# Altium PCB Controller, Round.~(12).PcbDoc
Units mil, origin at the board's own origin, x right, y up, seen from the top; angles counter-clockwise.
Board outline 1800 x 1800 mil, 2 copper layers (Top Layer, Bottom Layer); 50 components, 49 nets, 210 pads, 0 vias.
Unrouted connection lines stored in the file: 130.
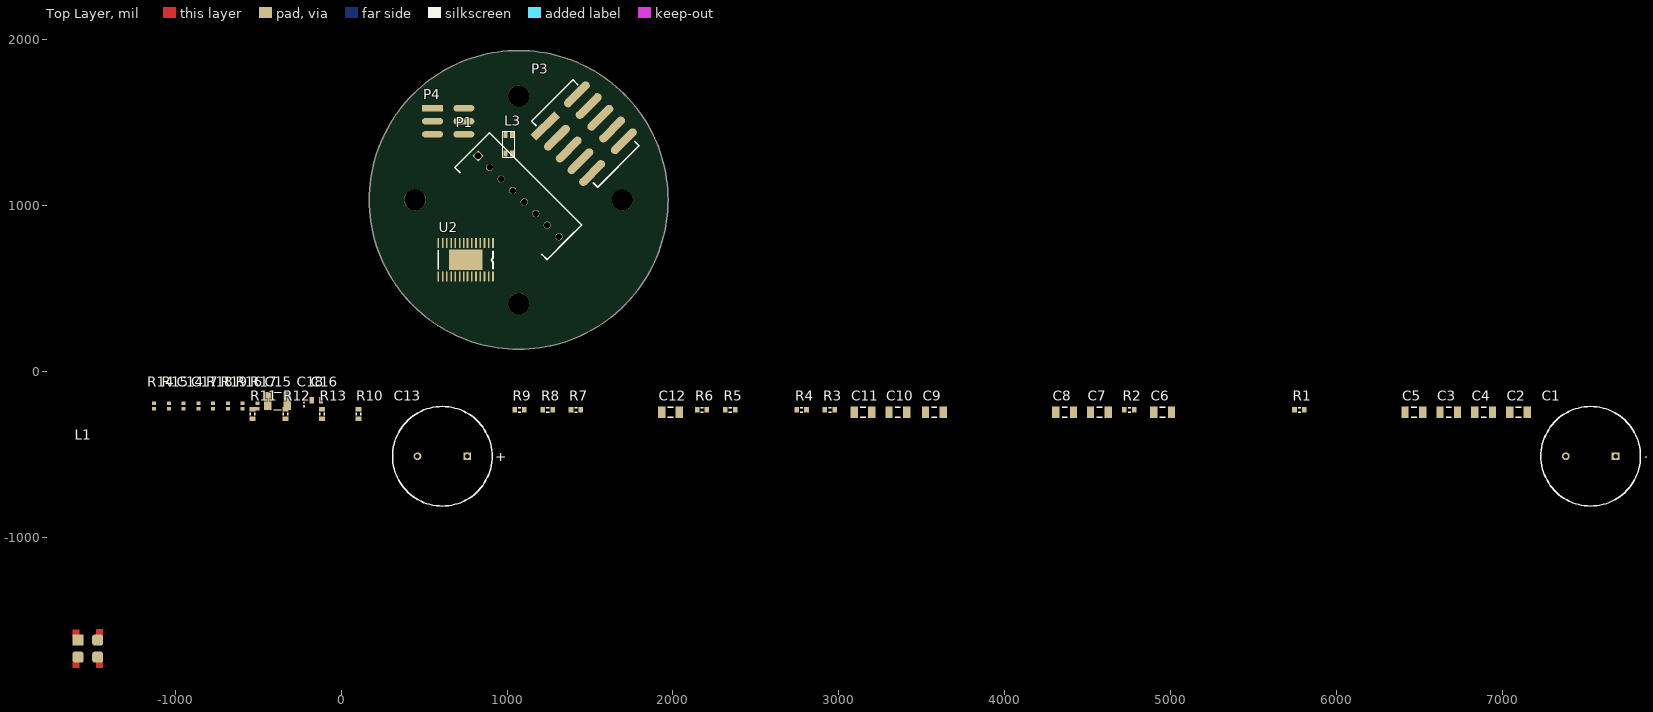
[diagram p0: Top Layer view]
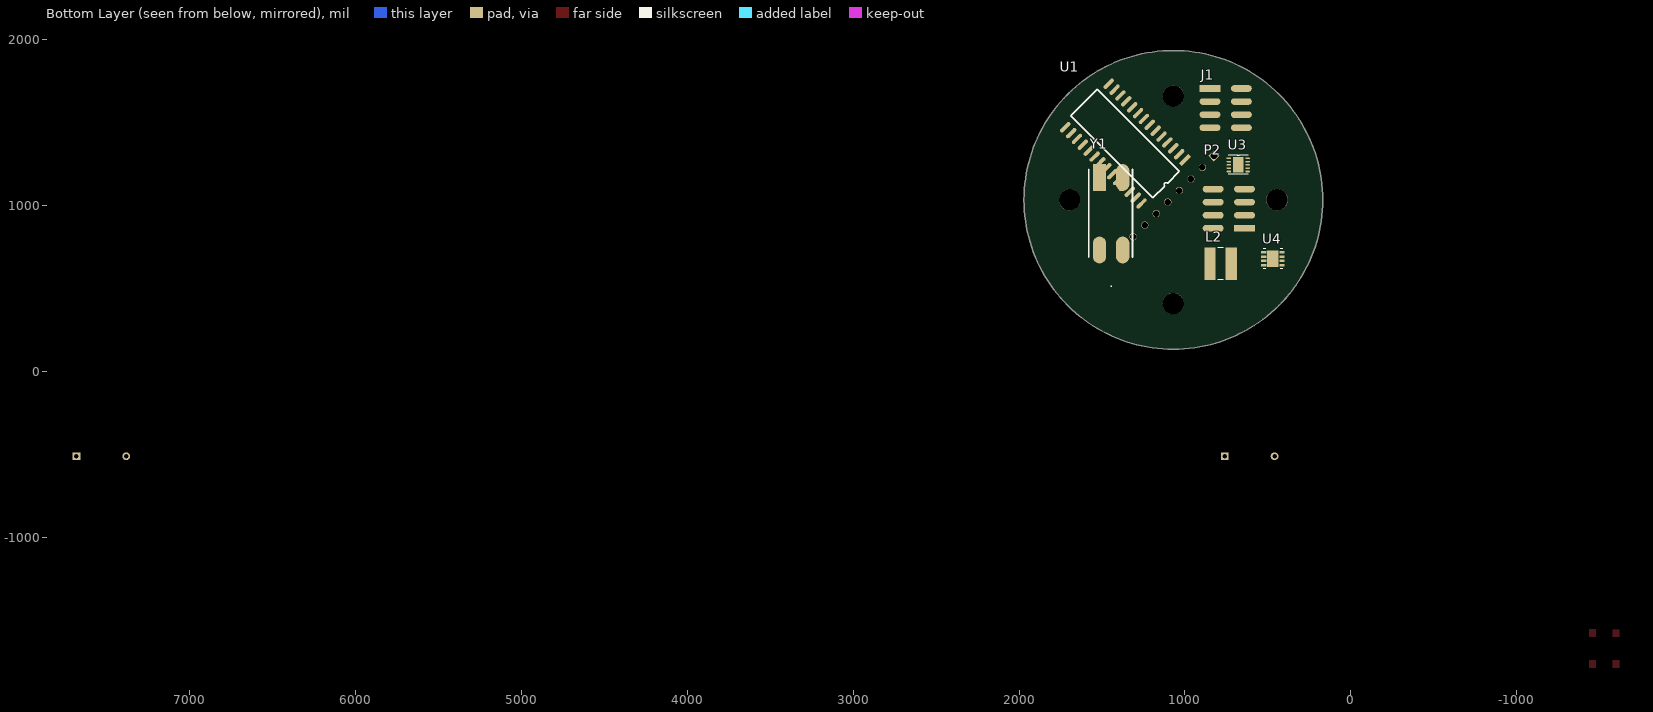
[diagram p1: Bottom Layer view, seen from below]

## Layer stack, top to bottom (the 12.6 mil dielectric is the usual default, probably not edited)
Top Layer: signal copper 1.4
Dielectric: dielectric 12.6, FR-4, Dk 4.8
Bottom Layer: signal copper 1.4

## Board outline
1070,135 cw(c1070,1035) 170,1035 cw(c1070,1035) 1070,1935 cw(c1070,1035) 1970,1035 cw(c1070,1035)

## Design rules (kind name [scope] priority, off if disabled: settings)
Clearance [All] p1: gap=10
PolygonConnect [All] p1: connectstyle=Relief reliefconductorwidth=10 reliefentries=4 polygonreliefangle="90 Angle"
RoomDefinition Controller [InComponentClass('Controller')] p1: confinementstyle=ConfineIn formatcopy=TRUE lockcomponents=FALSE outline -1190,-1020 8060,-1020 8060,-100 -1190,-100
RoutingVias [All] p1: holewidth=28 width=50 viastyle="Through Hole" minholewidth=28 minwidth=50 maxholewidth=28 maxwidth=50
SilkscreenOverComponentPads [All] p1: minsilkscreentomaskgap=10
SolderMaskExpansion [All] p1: expansion=4
Width [All] p1: maxlimit=10 minlimit=10 preferedwidth=10
27 further rules are at their usual default settings.

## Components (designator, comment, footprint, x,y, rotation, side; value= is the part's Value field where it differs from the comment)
C1 "Cap Pol1" RB7.6-15 7530,-510 r0 top
C2 "Cap Semi" C1206 7095,-245 r0 top
C3 "Cap Semi" C1206 6675,-245 r0 top
C4 "Cap Semi" C1206 6885,-245 r0 top
C5 "Cap Semi" C1206 6465,-245 r0 top
C6 "Cap Semi" C1206 4950,-245 r0 top
C7 "Cap Semi" C1206 4570,-245 r0 top
C8 "Cap Semi" C1206 4360,-245 r0 top
C9 "Cap Semi" C1206 3575,-245 r0 top
C10 "Cap Semi" C1206 3355,-245 r0 top
C11 "Cap Semi" C1206 3145,-245 r0 top
C12 "Cap Semi" C1206 1985,-245 r0 top
C13 "Cap Pol1" RB7.6-15 610,-510 r0 top
C14 "C1005X7R1E103K" 0402 -949.05,-206.31 r90 top
C15 "C3225X7R2A225K230AB" 1210 -383.13,-177 r0 top
C16 "C1608X5R0J106M" 0603 -148.84,-172.98 r0 top
C17 "C0402C330J5GAC" 0402 -860.06,-206.31 r90 top
C18 "GRM033R61A472KA01D" 0201 -223.84,-197.98 r90 top
J1 "M80-8280842" M8082808DIL 660,1470 r0 bottom
L1 "DLW5BTM501SQ2" DLW5A_5B -1585,-1720 r90 top
L2 "LPS5030-823MLB" LPS5030 785,650 r180 bottom
L3 "SRF3216-222Y" SRF3216 1030,1315 r180 top
P1 "MKS 1658-6-0-808" MKS_1658_A_KF 825,1300 r315 top
P2 "M80-8280842" M8082808DIL 830,1100 r180 bottom
P3 "N2510-6V0C-RB-WD" N2510_SMD 1230,1480 r45 top
P4 "M80-8280642" M8082806DIL 740,1430 r180 top
R1 "Res3" J1-0603 5775,-230 r0 top
R2 "Res3" J1-0603 4750,-230 r0 top
R3 "Res3" J1-0603 2945,-230 r0 top
R4 "Res3" J1-0603 2775,-230 r0 top
R5 "Res3" J1-0603 2345,-230 r0 top
R6 "Res3" J1-0603 2175,-230 r0 top
R7 "Res3" J1-0603 1415,-230 r0 top
R8 "Res3" J1-0603 1245,-230 r0 top
R9 "Res3" J1-0603 1075,-230 r0 top
R10 "Res3" J1-0603 105,-255 r90 top
R11 "Res3" J1-0603 -535,-255 r90 top
R12 "Res3" J1-0603 -335,-255 r90 top
R13 "Res3" J1-0603 -115,-255 r90 top
R14 "CRCW0402665KFKED" 0402 -1127.02,-206.31 r90 top
R15 "CRCW040253K6FKED" 0402 -1038.03,-206.31 r90 top
R16 "CRCW040246K4FKED" 0402 -593.11,-206.31 r90 top
R17 "CRCW040242K2FKED" 0402 -504.13,-206.31 r90 top
R18 "CRCW040210K0FKED" 0402 -771.08,-206.31 r90 top
R19 "CRCW040280K6FKED" 0402 -682.1,-206.31 r90 top
U1 "PIC_SERVO_SC" SOP28 1000,1275 r315 bottom
U2 "DRV8313" ? 915,775 r270 top
U3 "LTC2864xDD" DD10 735,1285 r180 bottom
U4 "TPS54061DRBR" S-PVSON-N8 470,680 r180 bottom
Y1 "MA-506 10.0000M-C0" MA506 1515,1170 r180 bottom

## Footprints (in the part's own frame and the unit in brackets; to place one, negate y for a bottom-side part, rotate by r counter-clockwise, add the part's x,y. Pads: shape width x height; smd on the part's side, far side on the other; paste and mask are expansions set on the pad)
0201 [mil]
  rect 14x13 smd: 1(-11.5,0) 2(11.5,0)
0402 [mil]
  rect 22x24 smd: 1(-16.5,0) 2(16.5,0)
0603 [mil]
  rect 26x38 smd: 1(-27.5,0) 2(27.5,0)
1210 [mil]
  rect 44x106 smd: 1(-59,0) 2(59,0)
  silkscreen extent -24,-53 24,53
C1206 [mm] "Chip Capacitor, Body 3.2x1.6mm, IPC High Density"
  rect 1.1x1.7 smd: 1(-1.35,0) 2(1.35,0)
  silkscreen extent -0.4,-0.75 0.4,0.75, body extent -1.7,-0.9 1.7,0.9, height 1.3
DD10 [mm]
  rect 0.7x0.25 smd: 1(0,0)
  oval 0.7x0.25 smd: 2(0,-0.5) 3(0,-1) 4(0,-1.5) 5(0,-2) 6(2.85,-2) 7(2.85,-1.5) 8(2.85,-1) 9(2.85,-0.5) 10(2.85,0)
  rrect10% 1.65x2.38 smd: Pad(1.425,-1)
  silkscreen extent -0.1,-2.45 2.95,0.5
DLW5A_5B [mm]
  rect 1.7x1.7 smd: 1(2.6,0)
  rrect50% 1.7x1.7 smd: 2(0,0) 3(0,-3) 4(2.6,-3)
  Top Layer region: -1.65,-0.25 -0.45,-0.25 -0.45,0.85 -1.65,0.85
  Top Layer region: -1.65,-3.85 -0.45,-3.85 -0.45,-2.75 -1.65,-2.75
  Top Layer region: 3.05,-0.25 4.25,-0.25 4.25,0.85 3.05,0.85
  Top Layer region: 3.1,-3.85 4.3,-3.85 4.3,-2.75 3.1,-2.75
J1-0603 [mm] "Chip Resistor, Body 1.6x0.8mm, IPC High Density"
  rect 0.7x0.9 smd: 1(-0.75,0) 2(0.75,0)
  silkscreen extent -0.2,-0.35 0.2,0.35, body extent -0.85,-0.48 0.85,0.48, height 0.9
LPS5030 [mil]
  rect 68.5x197 smd: 1(-64.25,0) 2(64.25,0)
  silkscreen extent -17,-96 17,96
M8082806DIL [mm] "Harwin 2x3"
  rect 3.2x1 smd: 1(4.8,-4)
  oval 3.2x1 smd: 2(0,-4) 3(4.8,-2) 4(0,-2) 5(4.8,0) 6(0,0)
M8082808DIL [mm] "Harwin M80-82808 SMT DIL Male Connector"
  rect 3.2x1 smd: 1(4.8,-6)
  oval 3.2x1 smd: 2(0,-6) 3(4.8,-4) 4(0,-4) 5(4.8,-2) 6(0,-2) 7(4.8,0) 8(0,0)
MA506 [mm]
  rect 2.05x4.1 smd: 1(0,0)
  oval 2.05x4.1 smd: 2(0,-11.1) 3(3.55,-11.1) 4(3.55,0)
  round 0.9 on Bottom Overlay: ""(-0.2,3.15)
  silkscreen extent -1.65,-16.65 5.05,1.26
MKS_1658_A_KF [mm] "Stocko MKS-1658 Shrouded Header Connector"
  rect 1.2x1.2 / inner rect 4x2.5 / far side rect 1.2x1.2 hole 1: 1(0,0)
  round 1.1 hole 1: 2(2.5,0) 3(5,0) 4(7.5,0) 5(10,0) 6(12.5,0) 7(15,0) 8(17.5,0)
  silkscreen extent -1.25,-3.75 18.7,3.75
N2510_SMD [mm]
  rect 5.08x1.27 smd: 1(0,0)
  oval 5.08x1.27 smd: 2(6.86,0) 3(0,-2.54) 4(6.86,-2.54) 5(0,-5.08) 6(6.86,-5.08) 7(0,-7.62) 8(6.86,-7.62) 9(0,-10.16) 10(6.86,-10.16)
  silkscreen extent -0.95,-12.3 8,2
RB7.6-15 [mm] "Polarized Capacitor (Radial); 2 Leads"
  rect 1.2x1.2 hole 0.7: 1(3.81,0)
  round 1.2 hole 0.7: 2(-3.81,0)
  silkscreen extent -7.62,-7.62 7.62,7.62
S-PVSON-N8 [mm]
  rect 0.805x0.37 smd: 1(-1.402,0.975) 2(-1.402,0.325) 3(-1.402,-0.325) 4(-1.402,-0.975) 5(1.402,-0.975) 6(1.402,-0.325) 7(1.402,0.325) 8(1.402,0.975)
  rect 1.75x2.5 smd paste-1.237: 9(0,0)
  silkscreen extent -1.5,-1.5 1.5,1.5
SOP28 [mm]
  rect 2x0.6 smd: 1(0,0)
  oval 2x0.6 smd: 2(0,-1.27) 3(0,-2.54) 4(0,-3.81) 5(0,-5.08) 6(0,-6.35) 7(0,-7.62) 8(0,-8.89) 9(0,-10.16) 10(0,-11.43) 11(0,-12.7) 12(0,-13.97) 13(0,-15.24) 14(0,-16.51) 15(9.4,-16.51) 16(9.4,-15.24) 17(9.4,-13.97) 18(9.4,-12.7) 19(9.4,-11.43) 20(9.4,-10.16) 21(9.4,-8.89) 22(9.4,-7.62) 23(9.4,-6.35) 24(9.4,-5.08) 25(9.4,-3.81) 26(9.4,-2.54) 27(9.4,-1.27) 28(9.4,0)
  silkscreen extent 1.83,-17.15 7.56,0.63
SRF3216 [mm]
  rect 0.6x0.9 smd: 1(0,0)
  rrect10% 0.6x0.9 smd: 2(0,-2.8) 3(1,-2.8) 4(1,0)
  silkscreen extent -0.4,-3.4 1.4,0.6
? [mm] "HTTSSOP 28 Pin Package, TI"
  rect 1.55x0.25 smd: 1(0,0)
  rrect50% 1.55x0.25 smd: 2(0,-0.65) 3(0,-1.3) 4(0,-1.95) 5(0,-2.6) 6(0,-3.25) 7(0,-3.9) 8(0,-4.45) 9(0,-5.1) 10(0,-5.75) 11(0,-6.4) 12(0,-7.05) 13(0,-7.7) 14(0,-8.35) 15(5.1,-8.35) 16(5.1,-7.7) 17(5.1,-7.05) 18(5.1,-6.4) 19(5.1,-5.75) 20(5.1,-5.1) 21(5.1,-4.45) 22(5.1,-3.9) 23(5.1,-3.25) 24(5.1,-2.6) 25(5.1,-1.95) 26(5.1,-1.3) 27(5.1,-0.65) 27(5.1,0)
  rect 3.1x5.18 smd: Pad(2.55,-4.15)
  silkscreen extent 1.15,-8.35 4,0

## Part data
C1 C13: "Polarized Capacitor (Radial)"
C2 C3 C4 C5 C6 C7 C8 C9 C10 C11 C12: "Capacitor (Semiconductor SIM Model)"
C15: "C3225X7R2A225K23"
C18: "GRM033R61A472KA0"
J1 P2: library part "Header 8", "Header, 8-Pin"
L1 L3: library part "COMMON MODE CHOKE"
P1: library part "Header 8"
P3: library part "Header 5X2", "Header, 5-Pin, Dual row"
P4: library part "Header 6", "Header, 6-Pin"
R1 R2 R3 R4 R5 R6 R7 R8 R9 R10 R11 R12 R13: "Resistor"
U4: "Imported"
Y1: library part MA-406/MA-505/MA-506

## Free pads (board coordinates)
  round 128.5 hole 128.5: ""(445,1035) ""(1070,410) ""(1070,1660) ""(1695,1035)

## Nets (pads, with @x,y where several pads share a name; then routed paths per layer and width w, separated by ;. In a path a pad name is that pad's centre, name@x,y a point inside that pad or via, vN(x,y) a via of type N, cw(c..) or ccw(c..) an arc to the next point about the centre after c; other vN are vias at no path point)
\ENC_A: P3.5
\ENC_B: P3.7
\ENC_INDEX: P3.9
\FAULT: R11.2 U1.3
ADDR_IN: U1.28
ADDR_OUT: U1.13
CUR_SENSE: C10.1 R3.2 U1.2 U2.17 U2.18 U2.19
ENC_A: P3.6 U1.5
ENC_B: P3.8 U1.6
ENC_INDEX: P3.10 R2.1
GND: C1.2 C3.1 C4.1 C9.1 C13.2 L1.3 R4.1 R5.1 R10.1 U2.14 U2.20 U2.Pad
HALL1: P1.6 R7.1 U1.25
HALL2: P1.7 R8.1 U1.26
HALL3: P1.8 R9.1 U1.27
LIMIT1: P4.2 R13.2 U1.16
LIMIT2: P4.5 R12.2 U1.14
NetC5_2: C5.2 U1.9 Y1.1
NetC7_2: C7.2 U1.10 Y1.4
NetC10_2: C10.2 R3.1 R4.2 U2.13
NetC14_1: C14.1 L2.2 U4.8
NetC14_2: C14.2 U4.1
NetC15_1: C15.1 L3.2 R14.1 U4.2
NetC17_1: C17.1 R16.2 U4.6
NetC18_1: C18.1 R16.1
NetJ1_1: J1.1 L1.4 L3.4 P2.1
NetJ1_2: J1.2 L1.1 L3.1 P2.2
NetP1_2: P1.2 U2.6
NetP1_3: P1.3 U2.5
NetR2_2: R2.2 U1.15
NetR14_2: R14.2 R17.1 U4.3
NetR15_2: R15.2 R18.1 U4.5
NetR19_1: R19.1 U4.4
NetU1_4: U1.4 U2.24
NetU1_11: U1.11 U2.22
NetU1_12: U1.12 U3.3
NetU1_17: U1.17 U3.4
NetU1_18: U1.18 U3.1
NetU1_21: U1.21 U2.27
NetU1_22: U1.22 U2.25
NetU1_23: U1.23 U2.23
NetU1_24: U1.24 U2.26
RS422_RX_A: J1.3 P2.3 U3.9
RS422_RX_B: J1.4 P2.4 U3.8
RS422_TX_A: J1.5 P2.5 U3.7
RS422_TX_B: J1.6 P2.6 U3.6
SGND: C2.2 C5.1 C7.1 C11.1 C12.2 C15.2 C16.2 C17.2 C18.2 L3.3 P1.5 P3.3 P4.4 P4.6 R10.2 R17.2 R18.2 R19.2 U1.8 U1.19 U3.5 U3.Pad U4.7
VCC: C2.1 C11.2 C12.1 C16.1 L2.1 P1.4 P3.2 P4.1 P4.3 R1.1 R7.2 R8.2 R9.2 R11.1 R12.1 R13.1 R15.1 U1.1 U1.7 U1.20 U3.10
VM: C1.1 C3.2 C4.2 C6.2 C13.1 L1.2 U2.4 U2.11
VSENSE: R5.2 R6.1 U2.9 U2.10
pads on no net: C6.1 C8.1 C8.2 C9.2 J1.7 J1.8 P1.1 P2.7 P2.8 P3.1 P3.4 R1.2 R6.2 U2.1 U2.2 U2.3 U2.7 U2.8 U2.12 U2.15 U2.16 U2.21 U3.2 U4.9 Y1. Y1.2 Y1.3

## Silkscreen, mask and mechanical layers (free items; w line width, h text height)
Mechanical 1:
  circle w5: c1070,1660 r64.25
  circle w5: c1695,1035 r64.25
  circle w5: c1070,410 r64.25
  circle w5: c445,1035 r64.25
  circle w5: c1070,1035 r900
